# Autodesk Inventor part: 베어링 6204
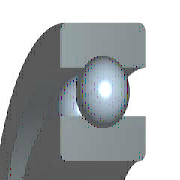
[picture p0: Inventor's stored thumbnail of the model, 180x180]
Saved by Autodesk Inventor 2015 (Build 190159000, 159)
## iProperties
IsCustomPart: 0
Created: 2015-12
Part Number: 베어링 6204
Material: 강철, 연강
Description: 깊은 그루브 볼 베어링
Document SubType Name: Modeling
Standard: KS B 2023
Designer: mdu
Standards Organization: KS
Language: ko-KR
Size Designation: 6204 - 20 x 47 x 14
Categories: <MemberInstance><Categories><Category DisplayName="샤프트 부품" InternalName="7f7aeb1f-a693-4053-b835-cee3144e0d98" Mnemonic="SHFT"><Category DisplayName="베어링" Inter
Density: 7.86 g/cm^3
Mass: 104.255 g
Surface Area: 87.8912 cm^2
Volume: 13.264 cm^3
Appearance: 강철
Author: mud
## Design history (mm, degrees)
sketch "스케치" dims "d0" = 7.02 (= -0.26 x WD + 0.26 x BD)
  geometry: L1 (3.49, 16.75)-(10.51, 16.75); L2 (7, 16.75)-(7, 13.24); L3 (7, 16.75)-(7, 20.26); L4 (4.392, 14.401)-(0, 14.401); L5 (0, 10)-(14, 10); L6 (4.392, 19.099)-(0, 19.099); L7 (0, 23.5)-(14, 23.5); L8 (14, 10)-(14, 14.401); L9 (9.608, 14.401)-(14, 14.401); L10 (9.608, 19.099)-(14, 19.099); L11 (14, 23.5)-(14, 19.099); L12 (-1.4, 0)-(8.4, 0) reference; L13 (0, -0.3)-(0, 5.3) reference
  constraints: 22 end point, 4 point on line, 2 collinear, 2 perpendicular, 2 symmetric about line, 1 midpoint, 1 parallel, 14 other
  dimensions: "d9" = 20 diameter of L5 L12 (= WD); "d11" = 47 diameter of L7 L12 (= BD); "d12" = 14 distance between parallel lines of L8 L13 (= KB); "d13" = 28.802 diameter of L9 L12 (= 0.326 x BD + 0.674 x WD)
revolve "본체" stored, may be unused: angle "d6" = 90 deg
revolve "볼" stored, may be unused: angle "d7" = 90 deg
pattern_circular "IDS_ARRAYBALL[SIMPL:T]" dims angle "d3" = 360 deg
body "Solid1"
fillet "모깎기1" dims "d1" = 1 (= KRS)
other parameters: "WD" = 20 [user parameter; used in 5 equation terms], "BD" = 47 [user parameter; used in 5 equation terms], "KB" = 14 [user parameter; used in 1 equation term], "KRS" = 1 [user parameter; used in 1 equation term], "d4" = 0, "d5" = 0, "d8" = 0, "d14" = 0, "d15" = 0, "BBA" = 0 [user parameter], "BC0" = 6550000 [user parameter], "BC" = 1.27e+07 [user parameter], "BR" = 23.5 (= 0.5 x BD) [user parameter]
